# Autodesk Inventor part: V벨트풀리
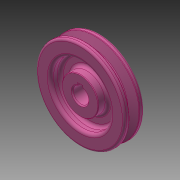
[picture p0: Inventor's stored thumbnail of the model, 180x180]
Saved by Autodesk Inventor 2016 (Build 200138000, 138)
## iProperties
Created: 2018-11
Part Number: V벨트풀리
Material: 알루미늄 6061
Document SubType Name: Modeling
Designer: mduedu
Density: 1 g/cm^3
Appearance: 분홍색
Author: mduedu
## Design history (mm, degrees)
sketch "스케치1"
  geometry: L1 (-9.5, 0)-(9.5, 0); L2 (9.5, 0)-(9.5, 42.7); L3 (9.5, 42.7)-(4.877, 42.7); L4 (-9.5, 42.7)-(-9.5, 0); L5 (-4.877, 42.7)-(-1.953, 33.7); L6 (-1.953, 33.7)-(1.953, 33.7); L7 (1.953, 33.7)-(4.877, 42.7); L8 (0, 0)-(0, 42.7); L9 (-9.5, 40)-(9.5, 40); L10 (-4.877, 42.7)-(-9.5, 42.7); L11 (4.877, 42.7)-(-4.877, 42.7); 3 further points
  constraints: 22 end point, 6 point on line, 4 parallel, 3 perpendicular, 2 midpoint, 1 coincident, 1 horizontal, 1 vertical, 1 other
  dimensions: "d2" = 19 distance of L2.end L4.start; "d3" = 80 diameter of L9 L1; "d4" = 36 deg angle of L7 L5; "d5" = 6.3 distance between parallel lines of L6 L9; "d6" = 8 distance of point (4, 40) point (-4, 40); "d27" = 2.7 distance between parallel lines of L3 L9
revolve "회전1" sketch "스케치1" stored, may be unused: angle "d7" = 90 deg
sketch "스케치2"
  geometry: L1 (-2.5, 7.071)-(2.5, 7.071); L2 (2.5, 7.071)-(2.5, 9.8); L3 (2.5, 9.8)-(-2.5, 9.8); L4 (-2.5, 9.8)-(-2.5, 7.071); A1 r 7.5 centre (0, 0) between (-2.5, 7.071) and (2.5, 7.071); 1 further point
  constraints: 8 end point, 2 parallel, 2 point on circle, 1 centre point, 1 coincident, 1 horizontal, 1 perpendicular
  dimensions: "d8" = 15 diameter of A1; "d10" = 17.3 dimension on A1 L3; "d11" = 5 distance of L2.end L3.end
extrude "돌출1" cut sketch "스케치2" stored distance "d12" = 10; taper "d13" = 0 deg
chamfer "모따기1" distance "d14" = 1; stored, may be unused: second distance "d15" = 2, angle "d16" = 45 deg
fillet "모깎기1" dims "d17" = 1, "d18" = 0.5, "d19" = 2
sketch "스케치3"
  geometry: C1 r 17.5 at (0, 0); C2 r 28.5 at (0, 0); 1 further point
  constraints: 2 centre point, 2 coincident
  dimensions: "d20" = 35 diameter of C1; "d23" = 57 diameter of C2
extrude "돌출2" cut sketch "스케치3" distance "d24" = 9.5; taper "d25" = 0 deg
fillet "모깎기2" dims "d26" = 3
chamfer "모따기2" distance "d28" = 0.5; stored, may be unused: second distance "d29" = 2, angle "d30" = 45 deg
node "솔리드1"
